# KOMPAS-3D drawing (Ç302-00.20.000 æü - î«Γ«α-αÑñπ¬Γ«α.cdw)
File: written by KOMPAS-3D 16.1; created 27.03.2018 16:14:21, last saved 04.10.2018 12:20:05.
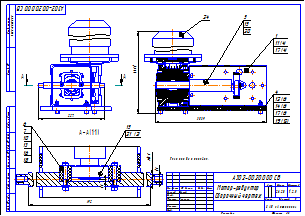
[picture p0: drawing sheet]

Sheet 1: A3, landscape

Title block, sheet 1: name: Мотор-редуктор / Сборочный чертеж; mass: 26,28; scale: 1:2,5; sheets: 1; organisation: ЗАО «Астерион»; sheet format: A3; stored path: Z:\Пресс-формы\РТМ технология\Магна 32\А302-00.20.000 СБ - Мотор-редуктор.cdw; drawn by: Милов; technical control: Лучихин

Views: Разрез А-А
Referenced files in \\192.168.87.28\Konstructor_doc\Мембранные насосы\Мембранный электропривод\А302-00.00.000 - ASTRA-302 (МЭ200)\Чертежи\: А302-00.20.001 - Основание.cdw, А302-00.35.000 - Фланец.cdw, А302-00.20.003 - Ползун.cdw
Referenced files in Z:\Мембранные насосы\Мембранный электропривод\А302-00.00.000 - ASTRA-302 (МЭ200)\Чертежи\: А302-00.20.002 - Эксцентрик.cdw, А302-00.20.004 - Вал.cdw, А302-00.20.000  - Мотор-редуктор.spw
Referenced files: graphic.tdp
Referenced files in Z:\Мембранные насосы\Мембранный электропривод\А302-00.00.000 - ASTRA-302 (МЭ200)\3Д\: А302-00.20.000 - Мотор-редуктор.a3d, А302-00.20.001 - Основание.m3d, А302-00.35.002 - Пластина.m3d, А302-00.35.001 - Труба 140х140х4.m3d, А302-00.35.000 - Фланец.a3d, А302-00.20.002 - Эксцентрик.m3d, А302-00.20.004 - Вал.m3d, А302-00.20.003 - Ползун.m3d
Referenced files in Z:\1 ПКИ 3D\Двигатели\АИР\: Электродвигатель АИР 80А4 IM 3081 1,1кВт 1400 об..m3d
Referenced files in Z:\1 ПКИ 3D\Редуктора NMRW\Редукторы\: Редуктор NMRW 063.m3d, Червячный мотор-редуктор NMRV063 АИР80.a3d
Referenced files in C:\Program Files\ASCON\KOMPAS-3D V16\Libs\PartLib\DATA\vault\Methods\Kompas\3D\: PLib_Check_spring_rings_GOST_13942_911.m3d, PLib_Washer_1_712.m3d, PLib_Washer_2_712.m3d, PLib_Nut_OST92_900.m3d, PLib_Screw_DIN_7984_1500.m3d, PLib_Key_prismatic_712.m3d
Referenced files in Z:\1 ПКИ 3D\1 Крепеж стандартный\Подшипник\: Подшипник 52х25х15 62052RSH SKF.m3d
Referenced files in C:\Program Files\ASCON\KOMPAS-3D V16\Libs\PartLib\DATA\VAULT\Methods\kompas\3d\: PLib_Bolt_1_900.m3d, PLib_Washer_2_712.m3d, PLib_Washer_1_712.m3d
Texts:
  Размеры для справок.
  Кольцо A25.65Г ГОСТ 13942-86
  Крепежное изделие ГОСТ
  Кольцо
  ГОСТ
  Сталь 65Г ГОСТ 14959-79
  Шайба C.5.04.019 ГОСТ 11371-78
  Шайба
  Сталь 20 ГОСТ 1050-2013
  Болт М5-6gx35.58.019 ГОСТ 7805-70
  Болт
  Шайба 5 30Х13 019 ГОСТ 6402-70
  Сталь 30Х13 ГОСТ 5632-72
  Гайка М5-6H.5.019 ГОСТ 5915-70
  Гайка
  Шайба C.8.04.019 ГОСТ 11371-78
  Шайба 8 30Х13 019 ГОСТ 6402-70
  Винт с цилиндрической головкой и
  шестигранным углублением под ключ
  ГОСТ Р ИСО  4762-М8 x 20-6.8-A9J
  Винт с цилиндрической головкой и шестигранным углублением под ключ
  Р ИСО
  Сталь
  ГОСТ Р ИСО  4762-М8 x 35-6.8-A9J
  Гайка М8-6H.5.019 ГОСТ 5915-70
  Винт с цилиндрической головкой и шестигранным углублением под ключ ГОСТ Р ИСО  4762-М8 x 35-6.8-A9J
  NMRV063 N 1,1кВт V5
  i - передат. отнош. см. заказ на сб.
  Мотор-редуктор / NMRV063 N 1,1кВт V5 / i - передат. отнош. см. заказ на сб.
  Двигатель
  Двигатель1400 об/минN=1400/i
  Основание
  Фланец
  Эксцентрик
  Подшипник 52х25х15 62052RSH SKF
  Подшипник
  RSH
  SKF
  Вал
  Ползун
  Шпонка 8 x 7 x 90 ГОСТ 23360-78
  Шпонка
  Лит-Масса-Масштаб
  Материал-Предприятие
  Title Specification
  Body Specification ( left align )
  Body Specificaton ( centered )
  Поз.
  Кол.
  Приме-
  чание
  Таблица спецификации
  Электродвигатель АИР 80А4 IM 3081 1,1кВт 1400 об.
  Редуктор NMRW 063
  Червячный мотор-редуктор NMRV063 АИР80
  Пластина
  Труба 140х140х4
  Винт с цилиндрической головкой и шестигранным углублением под ключ ГОСТ Р ИСО 4762 - М8 x 20 - 6.8 - A9J
  Винт с цилиндрической головкой и шестигранным углублением под ключ ГОСТ Р ИСО 4762 - М8 x 35 - 6.8 - A9J
  Шпонка 8x7x90 ГОСТ 23360-78
Dimensions and other numbers on the sheet: 4; 58; 65Г; 019; 2; 1; 04; 40Х; 3; 30Х13; 5; 12; 8; 6.8; 1400 об/мин; 78; 1:2,5; 26,28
